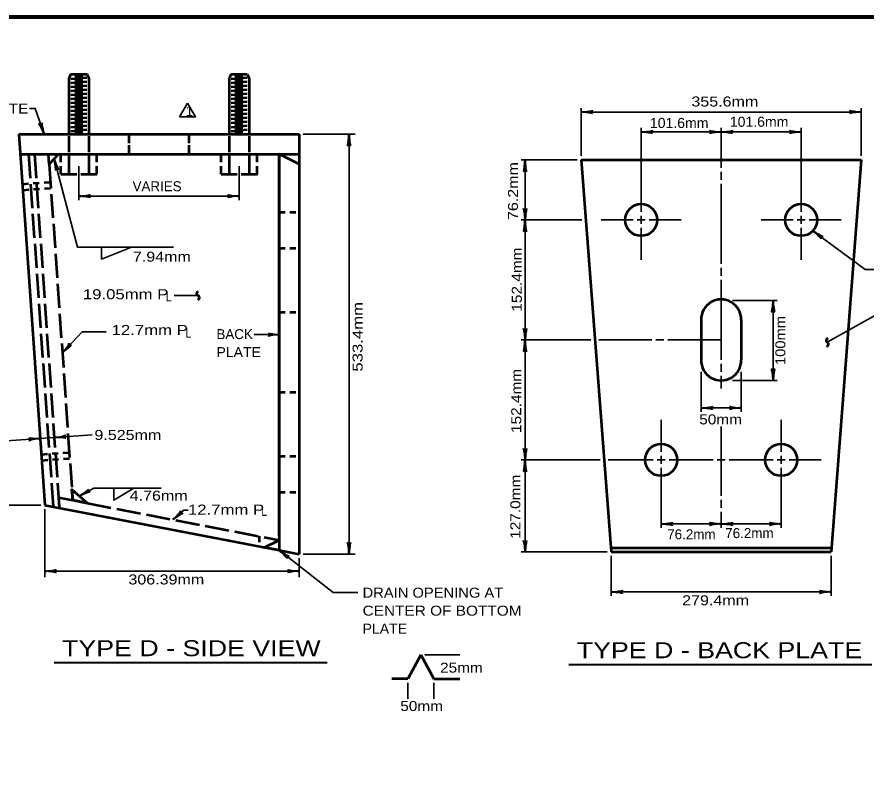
# Model space of a CAD drawing. Extents: x -35 to 821, y -23 to 522.
# Drawn here: x 256.3 to 511, y 288 to 515.2 of the extents above; entities that cross this region are included whole.
import ezdxf

# ---------------------------------------------------------------- set-up
doc = ezdxf.new("R2010")
doc.units = 0
doc.header["$LTSCALE"] = 1.2
doc.linetypes.add('LONG_DASHED', pattern=[7.5, 6, -1.5])
doc.linetypes.add('SHORT_DASHED', pattern=[2.7, 1.5, -1.2])
doc.layers.add('1', color=7, linetype='Continuous', lineweight=35)

msp = doc.modelspace()

# ---------------------------------------------------------------- linework, layer by layer
at = {"layer": '1', "lineweight": 53}
for p, q in [((272.53, 497.99), (271.93, 496.79)), ((271.93, 496.79), (271.93, 479.99)), ((272.53, 496.591), (277.33, 497.012)), ((273.673, 497.294), (276.082, 497.505)), ((277.93, 496.79), (277.93, 479.99)), ((320.53, 497.99), (319.93, 496.79)), ((319.93, 496.79), (319.93, 479.99)), ((320.53, 497.99), (325.33, 497.99)), ((320.53, 496.591), (325.33, 497.012)), ((321.673, 497.294), (324.082, 497.505)), ((325.33, 497.99), (325.93, 496.79)), ((325.93, 496.79), (325.93, 479.99)), ((272.53, 495.387), (277.33, 495.807)), ((272.53, 494.182), (277.33, 494.602)), ((273.673, 496.089), (276.082, 496.3)), ((273.673, 494.885), (276.082, 495.095)), ((320.53, 495.387), (325.33, 495.807)), ((320.53, 494.182), (325.33, 494.602)), ((321.673, 496.089), (324.082, 496.3)), ((321.673, 494.885), (324.082, 495.095)), ((272.53, 492.978), (277.33, 493.398)), ((272.53, 491.773), (277.33, 492.193)), ((273.673, 493.68), (276.082, 493.891)), ((273.673, 492.475), (276.082, 492.686)), ((320.53, 492.978), (325.33, 493.398)), ((320.53, 491.773), (325.33, 492.193)), ((321.673, 493.68), (324.082, 493.891)), ((321.673, 492.475), (324.082, 492.686)), ((272.53, 490.569), (277.33, 490.989)), ((272.53, 489.364), (277.33, 489.784)), ((273.673, 491.271), (276.082, 491.482)), ((273.673, 490.066), (276.082, 490.277)), ((273.673, 488.862), (276.082, 489.073)), ((320.53, 490.569), (325.33, 490.989)), ((320.53, 489.364), (325.33, 489.784)), ((321.673, 491.271), (324.082, 491.482)), ((321.673, 490.066), (324.082, 490.277)), ((321.673, 488.862), (324.082, 489.073)), ((272.53, 488.159), (277.33, 488.579)), ((272.53, 486.955), (277.33, 487.375)), ((273.673, 487.657), (276.082, 487.868)), ((273.673, 486.452), (276.082, 486.663)), ((320.53, 488.159), (325.33, 488.579)), ((320.53, 486.955), (325.33, 487.375)), ((321.673, 487.657), (324.082, 487.868)), ((321.673, 486.452), (324.082, 486.663)), ((272.53, 485.75), (277.33, 486.17)), ((272.53, 484.546), (277.33, 484.966)), ((273.673, 485.248), (276.082, 485.459)), ((273.673, 484.043), (276.082, 484.254)), ((320.53, 485.75), (325.33, 486.17)), ((320.53, 484.546), (325.33, 484.966)), ((321.673, 485.248), (324.082, 485.459)), ((321.673, 484.043), (324.082, 484.254)), ((272.53, 483.341), (277.33, 483.761)), ((272.53, 482.136), (277.33, 482.556)), ((272.53, 480.932), (277.33, 481.352)), ((273.673, 482.839), (276.082, 483.05)), ((273.673, 481.634), (276.082, 481.845)), ((320.53, 483.341), (325.33, 483.761)), ((320.53, 482.136), (325.33, 482.556)), ((320.53, 480.932), (325.33, 481.352)), ((321.673, 482.839), (324.082, 483.05)), ((321.673, 481.634), (324.082, 481.845)), ((256.93, 479.99), (340.93, 479.99)), ((256.93, 479.99), (264.715, 368.662)), ((271.93, 479.39), (271.93, 474.59)), ((273.673, 480.429), (276.082, 480.64)), ((277.93, 479.39), (277.93, 474.59)), ((289.93, 477.29), (289.93, 479.99)), ((307.93, 477.29), (307.93, 479.99)), ((319.93, 479.39), (319.93, 474.59)), ((321.673, 480.429), (324.082, 480.64)), ((325.93, 479.39), (325.93, 474.59)), ((289.93, 473.99), (289.93, 476.69)), ((307.93, 473.99), (307.93, 476.69)), ((257.35, 473.99), (268.77, 473.99)), ((265.979, 470.997), (265.77, 473.99)), ((268.77, 473.99), (340.93, 473.99)), ((269.53, 471.59), (269.53, 473.99)), ((271.93, 473.99), (271.93, 467.99)), ((277.93, 473.99), (277.93, 467.99)), ((280.33, 471.59), (280.33, 473.99)), ((317.53, 471.59), (317.53, 473.99)), ((319.93, 473.99), (319.93, 467.99)), ((325.93, 473.99), (325.93, 467.99)), ((328.33, 471.59), (328.33, 473.99)), ((334.93, 473.99), (334.93, 355.145)), ((334.93, 359.213), (334.93, 473.99)), ((425.526, 472.239), (509.526, 472.239)), ((425.526, 472.239), (434.526, 354.639)), ((509.526, 472.239), (500.526, 354.639)), ((269.53, 467.99), (269.53, 470.39)), ((280.33, 467.99), (280.33, 470.39)), ((317.53, 467.99), (317.53, 470.39)), ((269.53, 467.99), (274.33, 467.99)), ((275.53, 467.99), (280.33, 467.99)), ((317.53, 467.99), (322.33, 467.99)), ((461.526, 424.239), (461.526, 412.239)), ((473.526, 424.239), (473.526, 412.239)), ((272.806, 373.37), (273.034, 370.116)), ((273.034, 370.115), (277.436, 369.268)), ((264.715, 368.662), (334.93, 355.145)), ((334.93, 355.145), (340.93, 353.99)), ((434.434, 355.839), (500.618, 355.839)), ((434.526, 354.639), (500.526, 354.639)), ((377.487, 323.734), (373.587, 316.534)), ((377.487, 323.734), (381.387, 316.534)), ((373.587, 316.534), (368.787, 316.534)), ((381.387, 316.534), (389.187, 316.534))]:
    msp.add_line(p, q, dxfattribs=at)
at = {"layer": '1'}
for p, q in [((307.459, 489.313), (305.059, 485.156)), ((425.526, 473.439), (425.526, 487.839)), ((425.526, 486.639), (509.526, 486.639)), ((509.526, 473.439), (509.526, 487.839)), ((443.526, 456.639), (443.526, 481.839)), ((467.526, 481.839), (467.526, 469.839)), ((491.526, 456.639), (491.526, 481.839)), ((342.13, 479.99), (357.73, 479.99)), ((355.93, 479.99), (355.93, 353.99)), ((424.326, 472.239), (407.526, 472.239)), ((274.93, 470.39), (274.93, 460.19)), ((322.93, 470.39), (322.93, 460.19)), ((467.526, 468.639), (467.526, 466.239)), ((467.526, 465.039), (467.526, 441.039)), ((274.93, 461.39), (322.93, 461.39)), ((425.703, 454.239), (407.526, 454.239)), ((441.126, 454.239), (431.526, 454.239)), ((442.326, 454.239), (444.726, 454.239)), ((443.526, 455.439), (443.526, 453.039)), ((445.926, 454.239), (455.526, 454.239)), ((489.126, 454.239), (479.526, 454.239)), ((490.326, 454.239), (492.726, 454.239)), ((491.526, 455.439), (491.526, 453.039)), ((493.926, 454.239), (503.526, 454.239)), ((443.526, 451.839), (443.526, 442.239)), ((491.526, 451.839), (491.526, 442.239)), ((467.526, 439.839), (467.526, 437.439)), ((310.639, 431.531), (303.433, 431.531)), ((470.963, 430.08), (484.326, 430.08)), ((483.126, 430.08), (483.126, 406.08)), ((335.18, 419.83), (327.477, 419.83)), ((407.526, 418.239), (428.459, 418.239)), ((430.858, 418.239), (446.792, 418.239)), ((447.992, 418.239), (450.392, 418.239)), ((451.592, 418.239), (467.526, 418.239)), ((467.526, 411.039), (467.526, 408.639)), ((461.526, 408.639), (461.526, 396.639)), ((473.526, 408.639), (473.526, 396.639)), ((470.963, 406.08), (484.326, 406.08)), ((461.526, 397.839), (473.526, 397.839)), ((449.526, 384.639), (449.526, 394.239)), ((467.526, 392.244), (467.526, 371.439)), ((485.526, 384.639), (485.526, 394.239)), ((267.505, 388.976), (278.877, 389.771)), ((250.147, 387.762), (263.315, 388.683)), ((263.315, 388.683), (267.505, 388.976)), ((431.214, 382.239), (407.526, 382.239)), ((447.126, 382.239), (433.614, 382.239)), ((448.326, 382.239), (450.726, 382.239)), ((449.526, 381.039), (449.526, 383.439)), ((451.926, 382.239), (465.126, 382.239)), ((466.326, 382.239), (468.726, 382.239)), ((469.926, 382.239), (483.126, 382.239)), ((484.326, 382.239), (486.726, 382.239)), ((485.526, 381.039), (485.526, 383.439)), ((487.926, 382.239), (497.526, 382.239)), ((449.526, 379.839), (449.526, 361.839)), ((485.526, 379.839), (485.526, 361.839)), ((467.526, 370.239), (467.526, 367.839)), ((263.515, 368.662), (241.33, 368.662)), ((264.715, 367.462), (264.715, 347.062)), ((467.526, 366.639), (467.526, 361.839)), ((342.13, 353.99), (357.73, 353.99)), ((433.326, 354.639), (407.526, 354.639)), ((340.93, 352.79), (340.93, 347.062)), ((434.526, 353.439), (434.526, 341.439)), ((500.526, 353.439), (500.526, 341.439)), ((264.715, 348.862), (340.93, 348.862)), ((434.526, 342.639), (500.526, 342.639)), ((378.687, 323.734), (389.187, 323.734)), ((373.587, 315.334), (373.587, 310.534)), ((381.387, 315.334), (381.387, 310.534))]:
    msp.add_line(p, q, dxfattribs=at)
at = {"layer": '1', "linetype": 'LONG_DASHED', "lineweight": 53}
for p, q in [((259.756, 473.99), (267.154, 368.192)), ((261.56, 473.99), (268.983, 367.841)), ((265.979, 470.997), (272.803, 373.408)), ((268.766, 370.937), (273.034, 370.116)), ((277.452, 369.265), (334.93, 358.2))]:
    msp.add_line(p, q, dxfattribs=at)
at = {"layer": '1', "linetype": 'SHORT_DASHED', "lineweight": 53}
for p, q in [((257.977, 465.025), (266.356, 465.611)), ((258.102, 463.229), (266.482, 463.815)), ((334.93, 456.568), (340.93, 456.568)), ((334.93, 445.768), (340.93, 445.768)), ((334.93, 426.568), (340.93, 426.568)), ((334.93, 402.568), (340.93, 402.568)), ((263.65, 383.895), (272.029, 384.481)), ((263.775, 382.099), (272.155, 382.685)), ((334.93, 383.368), (340.93, 383.368)), ((334.93, 372.568), (340.93, 372.568)), ((328.93, 359.355), (328.93, 356.3))]:
    msp.add_line(p, q, dxfattribs=at)
at = {"layer": '1', "lineweight": 40}
for p, q in [((267.483, 321.452), (349.317, 321.452)), ((421.861, 320.845), (512.69, 320.845))]:
    msp.add_line(p, q, dxfattribs=at)
at = {"layer": '1', "lineweight": 158}
msp.add_lwpolyline([(814.415, 515.153), (22.715, 515.053), (22.815, -10.947)], dxfattribs=at)
at = {"layer": '1', "lineweight": 53}
for points in [[(272.53, 497.99), (277.33, 497.99), (277.93, 496.79)], [(340.93, 479.99), (340.93, 473.99), (340.93, 353.99)], [(323.53, 467.99), (328.33, 467.99), (328.33, 470.39)]]:
    msp.add_lwpolyline(points, dxfattribs=at)
at = {"layer": '1'}
for points in [[(307.459, 489.313), (309.859, 485.156), (305.059, 485.156)], [(264.449, 479.99), (261.789, 487.707), (260.11, 487.707)], [(443.526, 480.639), (467.526, 480.639), (491.526, 480.639)], [(267.482, 472.609), (274.433, 446.084), (303.233, 446.084)], [(408.726, 472.239), (408.726, 454.239), (408.726, 418.239), (408.726, 382.239), (408.726, 354.639)], [(495.07, 451.002), (510.694, 439.424), (517.508, 439.424)], [(281.632, 446.084), (281.632, 442.484), (290.67, 446.084)], [(467.526, 436.239), (467.526, 430.397), (467.526, 412.239)], [(499.368, 417.537), (514.706, 426.187), (522.054, 426.187)], [(269.937, 414.402), (275.926, 420.693), (283.117, 420.693)], [(467.526, 407.439), (467.526, 406.08), (467.526, 403.68)], [(275.058, 371.399), (279.414, 373.757), (299.623, 373.757)], [(285.414, 373.757), (285.414, 370.156), (291.349, 373.757)], [(303.116, 364.324), (306.416, 367.175), (307.679, 367.175)], [(449.526, 363.039), (467.526, 363.039), (485.526, 363.039)], [(334.93, 355.145), (351.166, 342.473), (358.517, 342.473)]]:
    msp.add_lwpolyline(points, dxfattribs=at)
at = {"layer": '1', "lineweight": 53}
for points in [[(265.77, 473.99), (268.77, 473.99), (265.979, 470.997)], [(334.93, 473.99), (340.93, 473.99), (340.93, 470.99)], [(273.034, 370.115), (272.803, 373.408), (277.452, 369.265)], [(330.511, 355.996), (334.93, 358.2), (334.93, 355.145)]]:
    msp.add_lwpolyline(points, close=True, dxfattribs=at)
for centre in [(443.526, 454.239), (491.526, 454.239), (449.526, 382.239), (485.526, 382.239)]:
    msp.add_circle(centre, 4.8, dxfattribs=at)
for centre, radius, start, end in [((310.785, 432.128), 0.615, 101.71531, 256.28469), ((310.493, 430.933), 0.615, 281.71531, 76.28469), ((467.526, 424.395), 6.002, 358.50341, 181.49658), ((499.625, 418.095), 0.615, 90.71531, 245.28469), ((499.111, 416.978), 0.615, 270.71531, 65.28469), ((467.526, 412.082), 6.002, 178.50342, 1.49659)]:
    msp.add_arc(centre, radius, start, end, dxfattribs=at)
at = {"layer": '1', "lineweight": 40}
for centre, major_axis, ratio, start_param, end_param in [((426.87, 486.385), (-2.108, 0.211), 0.07063, 3.1407148, 5.41811), ((426.87, 486.385), (-2.108, 0.211), 0.07063, 3.1407148, 5.41811), ((426.835, 486.97), (-2.143, -0.187), 0.122415, 0.8963533, 3.1415927), ((426.835, 486.97), (-2.143, -0.187), 0.122415, 0.8963533, 3.1415927), ((508.216, 486.307), (2.143, 0.187), 0.122415, 0.8963533, 3.1415927), ((508.181, 486.893), (2.108, -0.211), 0.07063, 3.1407148, 5.41811), ((263.709, 481.12), (0.875, -1.965), 0.122415, 0.8963533, 3.1415927), ((264.251, 481.344), (0.488, -2.061), 0.07063, 3.1407148, 5.41811), ((355.676, 478.645), (0.211, 2.108), 0.07063, 3.1407148, 5.41811), ((355.676, 478.645), (0.211, 2.108), 0.07063, 3.1407148, 5.41811), ((356.262, 478.681), (-0.187, 2.143), 0.122415, 0.8963533, 3.1415927), ((356.262, 478.681), (-0.187, 2.143), 0.122415, 0.8963533, 3.1415927), ((444.87, 480.385), (-2.108, 0.211), 0.07063, 3.1407148, 5.41811), ((444.835, 480.97), (-2.143, -0.187), 0.122415, 0.8963533, 3.1415927), ((466.216, 480.307), (2.143, 0.187), 0.122415, 0.8963533, 3.1415927), ((466.216, 480.307), (2.143, 0.187), 0.122415, 0.8963533, 3.1415927), ((466.181, 480.893), (2.108, -0.211), 0.07063, 3.1407148, 5.41811), ((466.181, 480.893), (2.108, -0.211), 0.07063, 3.1407148, 5.41811), ((468.87, 480.385), (-2.108, 0.211), 0.07063, 3.1407148, 5.41811), ((468.87, 480.385), (-2.108, 0.211), 0.07063, 3.1407148, 5.41811), ((468.835, 480.97), (-2.143, -0.187), 0.122415, 0.8963533, 3.1415927), ((468.835, 480.97), (-2.143, -0.187), 0.122415, 0.8963533, 3.1415927), ((490.216, 480.307), (2.143, 0.187), 0.122415, 0.8963533, 3.1415927), ((490.181, 480.893), (2.108, -0.211), 0.07063, 3.1407148, 5.41811), ((267.577, 471.244), (0.33, -2.092), 0.07063, 6.2823074, 8.5597026), ((268.135, 471.426), (-0.724, 2.025), 0.122415, 0.8963533, 3.1415927), ((408.472, 470.894), (0.211, 2.108), 0.07063, 3.1407148, 5.41811), ((409.057, 470.929), (-0.187, 2.143), 0.122415, 0.8963533, 3.1415927), ((276.275, 461.136), (-2.108, 0.211), 0.07063, 3.1407148, 5.41811), ((276.275, 461.136), (-2.108, 0.211), 0.07063, 3.1407148, 5.41811), ((276.24, 461.722), (-2.143, -0.187), 0.122415, 0.8963533, 3.1415927), ((276.24, 461.722), (-2.143, -0.187), 0.122415, 0.8963533, 3.1415927), ((321.621, 461.059), (2.143, 0.187), 0.122415, 0.8963533, 3.1415927), ((321.585, 461.644), (2.108, -0.211), 0.07063, 3.1407148, 5.41811), ((408.394, 455.548), (0.187, -2.143), 0.122415, 0.8963533, 3.1415927), ((408.98, 455.583), (-0.211, -2.108), 0.07063, 3.1407148, 5.41811), ((408.472, 452.894), (0.211, 2.108), 0.07063, 3.1407148, 5.41811), ((409.057, 452.929), (-0.187, 2.143), 0.122415, 0.8963533, 3.1415927), ((495.999, 449.997), (-1.568, 1.424), 0.07063, 3.1407148, 5.41811), ((496.319, 450.488), (-1.833, 1.125), 0.122415, 0.8963533, 3.1415927), ((482.872, 428.735), (0.211, 2.108), 0.07063, 3.1407148, 5.41811), ((482.872, 428.735), (0.211, 2.108), 0.07063, 3.1407148, 5.41811), ((483.457, 428.77), (-0.187, 2.143), 0.122415, 0.8963533, 3.1415927), ((483.457, 428.77), (-0.187, 2.143), 0.122415, 0.8963533, 3.1415927), ((333.835, 420.084), (2.108, -0.211), 0.07063, 3.1407148, 5.41811), ((408.394, 419.548), (0.187, -2.143), 0.122415, 0.8963533, 3.1415927), ((408.98, 419.583), (-0.211, -2.108), 0.07063, 3.1407148, 5.41811), ((333.87, 419.498), (2.143, 0.187), 0.122415, 0.8963533, 3.1415927), ((408.472, 416.894), (0.211, 2.108), 0.07063, 3.1407148, 5.41811), ((409.057, 416.929), (-0.187, 2.143), 0.122415, 0.8963533, 3.1415927), ((270.6, 415.579), (-1.342, -1.681), 0.122415, 0.8963533, 3.1415927), ((271.048, 415.201), (1.606, 1.381), 0.07063, 6.2823074, 8.5597026), ((482.794, 407.389), (0.187, -2.143), 0.122415, 0.8963533, 3.1415927), ((483.38, 407.424), (-0.211, -2.108), 0.07063, 3.1407148, 5.41811), ((462.87, 397.585), (-2.108, 0.211), 0.07063, 3.1407148, 5.41811), ((462.87, 397.585), (-2.108, 0.211), 0.07063, 3.1407148, 5.41811), ((462.835, 398.17), (-2.143, -0.187), 0.122415, 0.8963533, 3.1415927), ((462.835, 398.17), (-2.143, -0.187), 0.122415, 0.8963533, 3.1415927), ((472.216, 397.507), (2.143, 0.187), 0.122415, 0.8963533, 3.1415927), ((472.181, 398.093), (2.108, -0.211), 0.07063, 3.1407148, 5.41811), ((268.788, 389.398), (-2.125, -0.336), 0.122415, 0.8963533, 3.1415927), ((268.788, 389.398), (-2.125, -0.336), 0.122415, 0.8963533, 3.1415927), ((261.956, 388.843), (2.117, -0.063), 0.07063, 3.1407148, 5.41811), ((262.032, 388.261), (2.125, 0.336), 0.122415, 0.8963533, 3.1415927), ((268.864, 388.816), (-2.117, 0.063), 0.07063, 3.1407148, 5.41811), ((268.864, 388.816), (-2.117, 0.063), 0.07063, 3.1407148, 5.41811), ((408.394, 383.548), (0.187, -2.143), 0.122415, 0.8963533, 3.1415927), ((408.98, 383.583), (-0.211, -2.108), 0.07063, 3.1407148, 5.41811), ((408.472, 380.894), (0.211, 2.108), 0.07063, 3.1407148, 5.41811), ((409.057, 380.929), (-0.187, 2.143), 0.122415, 0.8963533, 3.1415927), ((276.051, 372.314), (-1.795, -1.185), 0.122415, 0.8963533, 3.1415927), ((276.361, 371.816), (-1.954, -0.818), 0.07063, 3.1407148, 5.41811), ((303.891, 365.431), (-1.499, -1.543), 0.122415, 0.8963533, 3.1415927), ((304.3, 365.011), (-1.733, -1.218), 0.07063, 3.1407148, 5.41811), ((450.87, 362.785), (-2.108, 0.211), 0.07063, 3.1407148, 5.41811), ((450.87, 362.785), (-2.108, 0.211), 0.07063, 3.1407148, 5.41811), ((450.835, 363.37), (-2.143, -0.187), 0.122415, 0.8963533, 3.1415927), ((450.835, 363.37), (-2.143, -0.187), 0.122415, 0.8963533, 3.1415927), ((466.216, 362.707), (2.143, 0.187), 0.122415, 0.8963533, 3.1415927), ((466.216, 362.707), (2.143, 0.187), 0.122415, 0.8963533, 3.1415927), ((466.181, 363.293), (2.108, -0.211), 0.07063, 3.1407148, 5.41811), ((466.181, 363.293), (2.108, -0.211), 0.07063, 3.1407148, 5.41811), ((468.87, 362.785), (-2.108, 0.211), 0.07063, 3.1407148, 5.41811), ((468.87, 362.785), (-2.108, 0.211), 0.07063, 3.1407148, 5.41811), ((468.835, 363.37), (-2.143, -0.187), 0.122415, 0.8963533, 3.1415927), ((468.835, 363.37), (-2.143, -0.187), 0.122415, 0.8963533, 3.1415927), ((484.216, 362.707), (2.143, 0.187), 0.122415, 0.8963533, 3.1415927), ((484.216, 362.707), (2.143, 0.187), 0.122415, 0.8963533, 3.1415927), ((484.181, 363.293), (2.108, -0.211), 0.07063, 3.1407148, 5.41811), ((484.181, 363.293), (2.108, -0.211), 0.07063, 3.1407148, 5.41811), ((355.599, 355.3), (0.187, -2.143), 0.122415, 0.8963533, 3.1415927), ((356.184, 355.335), (-0.211, -2.108), 0.07063, 3.1407148, 5.41811), ((408.394, 355.948), (0.187, -2.143), 0.122415, 0.8963533, 3.1415927), ((408.98, 355.983), (-0.211, -2.108), 0.07063, 3.1407148, 5.41811), ((335.834, 354.118), (1.532, -1.463), 0.07063, 6.2823074, 8.5597026), ((336.166, 354.601), (-1.805, 1.171), 0.122415, 0.8963533, 3.1415927), ((266.024, 349.194), (-2.143, -0.187), 0.122415, 0.8963533, 3.1415927), ((266.024, 349.194), (-2.143, -0.187), 0.122415, 0.8963533, 3.1415927), ((339.585, 349.116), (2.108, -0.211), 0.07063, 3.1407148, 5.41811), ((339.585, 349.116), (2.108, -0.211), 0.07063, 3.1407148, 5.41811), ((266.06, 348.608), (-2.108, 0.211), 0.07063, 3.1407148, 5.41811), ((266.06, 348.608), (-2.108, 0.211), 0.07063, 3.1407148, 5.41811), ((339.621, 348.53), (2.143, 0.187), 0.122415, 0.8963533, 3.1415927), ((339.621, 348.53), (2.143, 0.187), 0.122415, 0.8963533, 3.1415927), ((435.87, 342.385), (-2.108, 0.211), 0.07063, 3.1407148, 5.41811), ((435.87, 342.385), (-2.108, 0.211), 0.07063, 3.1407148, 5.41811), ((435.835, 342.97), (-2.143, -0.187), 0.122415, 0.8963533, 3.1415927), ((435.835, 342.97), (-2.143, -0.187), 0.122415, 0.8963533, 3.1415927), ((499.216, 342.307), (2.143, 0.187), 0.122415, 0.8963533, 3.1415927), ((499.181, 342.893), (2.108, -0.211), 0.07063, 3.1407148, 5.41811)]:
    msp.add_ellipse(centre, major_axis=major_axis, ratio=ratio, start_param=start_param, end_param=end_param, dxfattribs=at)

# ---------------------------------------------------------------- texts
at = {"layer": '1'}
for s, height, width, p in [('TOP PLATE', 3, 1.15, (234.374, 486.171)), ('355.6mm', 3, 1.2, (458.61, 488.288)), ('101.6mm', 3, 1.05, (446.162, 481.861)), ('101.6mm', 3, 1.05, (470.132, 482.216)), ('7.94mm', 3, 1.2, (291.09, 441.715)), ('19.05mm P', 3, 1.25, (276.098, 430.46)), ('L', 3, 0.75, (301.021, 429.817)), ('12.7mm P', 3, 1.25, (284.71, 419.738)), ('L', 3, 0.75, (306.914, 418.917)), ('PLATE', 3, 1.05, (316.156, 413.092)), ('50mm', 3, 1.15, (460.961, 392.898)), ('9.525mm', 3, 1.2, (279.554, 388.238)), ('4.76mm', 3, 1.2, (290.136, 370.024)), ('12.7mm P', 3, 1.25, (307.615, 365.837)), ('L', 3, 0.75, (329.641, 365.46)), ('306.39mm', 3, 1.2, (289.75, 344.87)), ('DRAIN OPENING AT', 3, 1.1, (359.992, 340.906)), ('279.4mm', 3, 1.2, (455.83, 338.624)), ('CENTER OF BOTTOM', 3, 1.15, (359.992, 335.506)), ('PLATE', 3, 1.05, (359.992, 330.106)), ('TYPE D - SIDE VIEW', 4.8, 1.25, (269.853, 323.349)), ('TYPE D - BACK PLATE', 4.8, 1.25, (424.231, 322.742)), ('25mm', 3, 1.15, (383.231, 318.41)), ('50mm', 3, 1.15, (371.291, 306.895))]:
    msp.add_text(s, height=height, dxfattribs=dict(at, width=width)).set_placement(p)
for s, p in [('1', (306.917, 485.399)), ('VARIES', (291.001, 462.86)), ('BACK', (316.156, 418.492)), ('76.2mm', (468.762, 358.783)), ('76.2mm', (451.361, 358.428))]:
    msp.add_text(s, height=3, dxfattribs=at).set_placement(p)
for s, width, p in [('76.2mm', 1.2, (406.596, 454.222)), ('152.4mm', 1.15, (407.746, 426.723)), ('533.4mm', 1.25, (359.988, 408.734)), ('100mm', 1.1, (486.785, 410.719)), ('152.4mm', 1.15, (407.568, 390.315)), ('127.0mm', 1.15, (407.307, 358.569))]:
    msp.add_text(s, height=3, rotation=90, dxfattribs=dict(at, width=width)).set_placement(p)

doc.saveas('drawing.dxf')
